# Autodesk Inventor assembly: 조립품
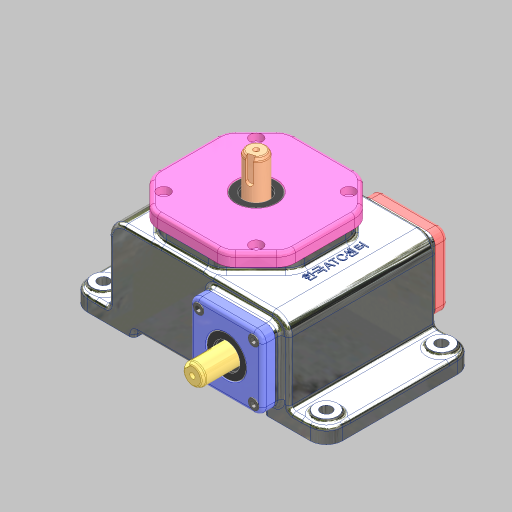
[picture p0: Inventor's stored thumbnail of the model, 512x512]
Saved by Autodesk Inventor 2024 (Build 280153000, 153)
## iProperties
Created: 2026-02
Part Number: 조립품
Document SubType Name: Assembly
Designer: 2-10
Author: 2-10
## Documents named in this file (13)
- C:\Users\2-10\Desktop\760203V1009\조립품.iam
- C:\Users\2-10\Desktop\760203V1009\조립품.ipt
- C:\Users\2-10\Desktop\760203V1009\웜 휠 커버\웜 휠 커버.ipt
- C:\Users\2-10\Desktop\760203V1009\6각 구멍붙이 볼트 M5x10\6각 구멍붙이 볼트 M5x10.ipt
- C:\Users\2-10\Desktop\760203V1009\뒷커버\뒷커버.ipt
- C:\Users\2-10\Desktop\760203V1009\앞커버\앞커버.ipt
- C:\Users\2-10\Desktop\760203V1009\오일 실 17 32 8\오일 실 17 32 8.ipt
- C:\Users\2-10\Desktop\760203V1009\웜 샤프트\웜 샤프트.ipt
- C:\Users\2-10\Desktop\760203V1009\웜 휠\웜 휠.ipt
- C:\Users\2-10\Desktop\760203V1009\축\축.ipt
- C:\Users\2-10\Desktop\760203V1009\칼라\칼라.ipt
- C:\Users\2-10\Desktop\760203V1009\테이퍼 롤러 베어링 30203\테이퍼 롤러 베어링 30203.ipt
- C:\Users\2-10\Desktop\760203V1009\평행 키 5x5x16\평행 키 5x5x16.ipt
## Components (8 placed, 1 different names)
1. 6각 구멍붙이 볼트 M5x10:1
2. 6각 구멍붙이 볼트 M5x10:2
3. 6각 구멍붙이 볼트 M5x10:3
4. 6각 구멍붙이 볼트 M5x10:4
5. 6각 구멍붙이 볼트 M5x10:5
6. 6각 구멍붙이 볼트 M5x10:6
7. 6각 구멍붙이 볼트 M5x10:7
8. 6각 구멍붙이 볼트 M5x10:8
